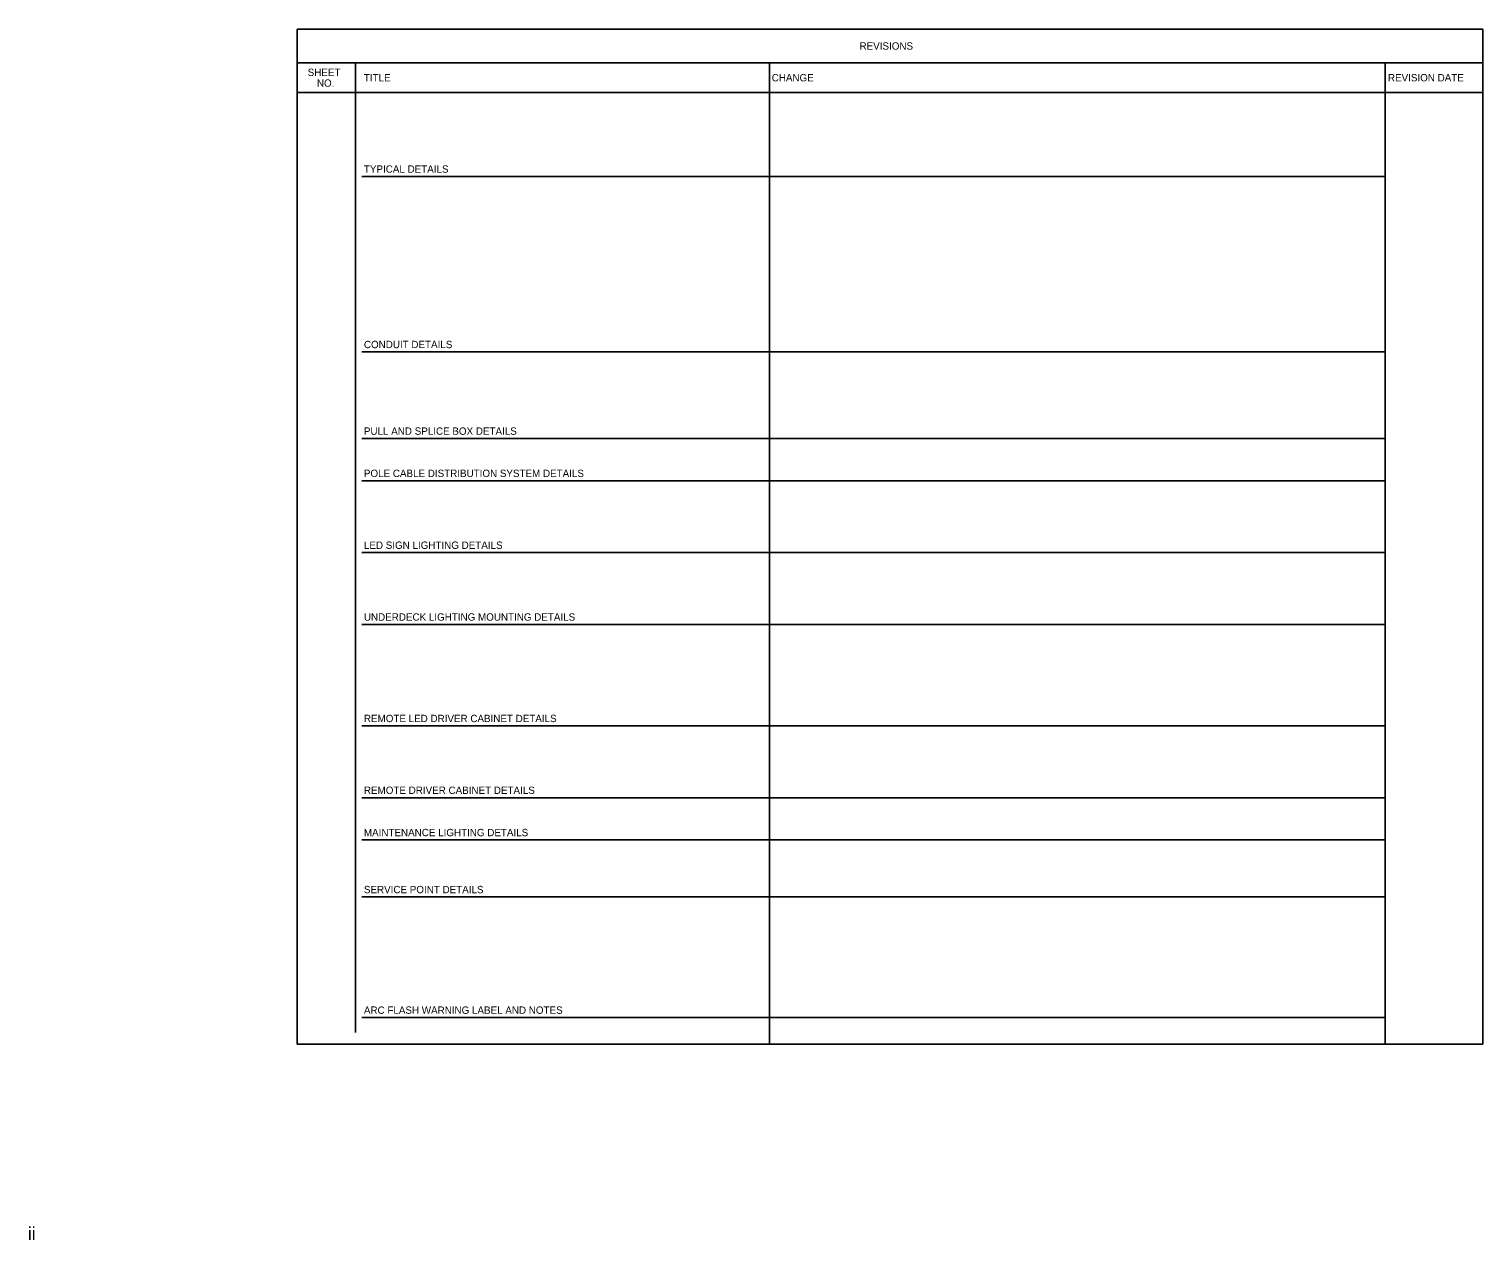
# Model space of a CAD drawing. Extents: x -39 to 1295, y -523 to -44.
# Drawn here: x 735 to 1295, y -511 to -44 of the extents above; entities that cross this region are included whole.
import ezdxf

# ---------------------------------------------------------------- set-up
doc = ezdxf.new("R2010")
doc.units = 0
for name, color, linetype in [('SumBoxLines_dp', 7, 'Continuous'), ('SumBoxLinesMin_dp', 7, 'Continuous'), ('TextLabel', 7, 'Continuous'), ('TextShtNo', 7, 'Continuous')]:
    doc.layers.add(name, color=color, linetype=linetype)

msp = doc.modelspace()

# ---------------------------------------------------------------- linework, layer by layer
at = {"layer": 'SumBoxLines_dp'}
for p, q in [((838.01, -43.57), (1295.31, -43.57)), ((838.01, -43.57), (838.01, -56.62)), ((1295.31, -43.57), (1295.31, -435.18)), ((838.01, -56.62), (1295.31, -56.62)), ((838.01, -56.62), (1295.31, -56.62)), ((860.48, -56.62), (860.48, -257.81)), ((860.48, -56.62), (860.48, -430.63)), ((1020.2, -56.62), (1020.2, -435.18)), ((1257.66, -56.62), (1257.66, -435.18)), ((1257.66, -56.62), (1257.66, -435.18)), ((838.01, -68.04), (1295.31, -68.04)), ((838.01, -68.04), (1295.31, -68.04)), ((862.91, -100.43), (1257.66, -100.43)), ((862.91, -100.43), (1257.66, -100.43)), ((862.91, -168.11), (1257.66, -168.11)), ((862.91, -168.11), (1257.66, -168.11)), ((862.91, -201.53), (1257.66, -201.53)), ((862.91, -201.53), (1257.66, -201.53)), ((862.91, -217.82), (1257.66, -217.82)), ((862.91, -217.82), (1257.66, -217.82)), ((862.91, -245.54), (1257.66, -245.54)), ((862.91, -245.54), (1257.66, -245.54)), ((860.48, -263.51), (860.48, -419.21)), ((862.91, -273.25), (1257.66, -273.25)), ((862.91, -273.25), (1257.66, -273.25)), ((862.91, -312.38), (1257.66, -312.38)), ((862.91, -312.38), (1257.66, -312.38)), ((862.91, -340.1), (1257.66, -340.1)), ((862.91, -340.1), (1257.66, -340.1)), ((862.91, -356.39), (1257.66, -356.39)), ((862.91, -356.39), (1257.66, -356.39)), ((862.91, -378.4), (1257.66, -378.4)), ((862.91, -378.4), (1257.66, -378.4)), ((862.91, -424.92), (1020.2, -424.92)), ((862.91, -424.92), (1257.66, -424.92))]:
    msp.add_line(p, q, dxfattribs=at)
at = {"layer": 'SumBoxLinesMin_dp'}
for p, q in [((838.01, -56.62), (838.01, -435.18)), ((838.01, -435.18), (1295.31, -435.18))]:
    msp.add_line(p, q, dxfattribs=at)

# ---------------------------------------------------------------- texts
at = {"layer": 'TextLabel'}
for s, height, p in [('REVISIONS', 2.834, (1054.88, -51.51)), ('SHEET', 2.834, (842.04, -61.68)), ('TITLE', 2.834, (863.72, -63.75)), ('CHANGE', 2.834, (1021.01, -63.75)), ('REVISION DATE', 2.8341, (1258.68, -63.75)), ('NO.', 2.834, (845.6, -65.81)), ('TYPICAL DETAILS', 2.8341, (863.72, -98.99)), ('CONDUIT DETAILS', 2.8341, (863.72, -166.67)), ('PULL AND SPLICE BOX DETAILS', 2.8341, (863.72, -200.09)), ('POLE CABLE DISTRIBUTION SYSTEM DETAILS', 2.8341, (863.72, -216.39)), ('LED SIGN LIGHTING DETAILS', 2.8341, (863.72, -244.1)), ('UNDERDECK LIGHTING MOUNTING DETAILS', 2.8341, (863.72, -271.81)), ('REMOTE LED DRIVER CABINET DETAILS', 2.8341, (863.72, -310.95)), ('REMOTE DRIVER CABINET DETAILS', 2.8341, (863.72, -338.66)), ('MAINTENANCE LIGHTING DETAILS', 2.8341, (863.72, -354.96)), ('SERVICE POINT DETAILS', 2.8341, (863.72, -376.96)), ('ARC FLASH WARNING LABEL AND NOTES', 2.8341, (863.72, -423.48))]:
    msp.add_text(s, height=height, dxfattribs=at).set_placement(p)
at = {"layer": 'TextShtNo'}
msp.add_text('  ii  ', height=5, dxfattribs=at).set_placement((730.42, -510.72))

doc.saveas('drawing.dxf')
